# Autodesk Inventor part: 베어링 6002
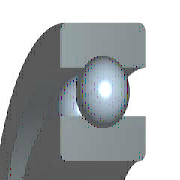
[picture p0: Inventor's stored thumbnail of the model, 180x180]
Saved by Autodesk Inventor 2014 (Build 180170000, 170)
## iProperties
IsCustomPart: 0
Created: 2012-02
Part Number: 베어링 6002
Material: 강철, 연강
Description: 깊은 그루브 볼 베어링
Document SubType Name: Modeling
Standard: KS B 2023
Designer: mduedu
Standards Organization: KS
Language: ko-KR
Size Designation: 6002 - 15 x 32 x 9
Categories: <MemberInstance><Categories><Category DisplayName="샤프트 부품" InternalName="7f7aeb1f-a693-4053-b835-cee3144e0d98" Mnemonic="SHFT"><Category DisplayName="베어링" Inter
Density: 7.86 g/cm^3
Mass: 29.8124 g
Surface Area: 39.9079 cm^2
Volume: 3.79293 cm^3
Appearance: 노란색
Author: mduedu
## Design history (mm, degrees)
sketch "스케치" dims "d0" = 4.42 (= -0.26 x WD + 0.26 x BD)
  geometry: L1 (2.29, 11.75)-(6.71, 11.75); L2 (4.5, 11.75)-(4.5, 9.54); L3 (4.5, 11.75)-(4.5, 13.96); L4 (2.858, 10.271)-(0, 10.271); L5 (0, 7.5)-(9, 7.5); L6 (2.858, 13.229)-(0, 13.229); L7 (0, 16)-(9, 16); L8 (9, 7.5)-(9, 10.271); L9 (6.142, 10.271)-(9, 10.271); L10 (6.142, 13.229)-(9, 13.229); L11 (9, 16)-(9, 13.229); L12 (-1.4, 0)-(8.4, 0) reference; L13 (0, -0.3)-(0, 5.3) reference
  constraints: 22 end point, 4 point on line, 2 collinear, 2 perpendicular, 2 symmetric about line, 1 midpoint, 1 parallel, 14 other
  dimensions: "d9" = 15 diameter of L5 L12 (= WD); "d11" = 32 diameter of L7 L12 (= BD); "d12" = 9 distance between parallel lines of L8 L13 (= KB); "d13" = 20.542 diameter of L9 L12 (= 0.326 x BD + 0.674 x WD)
revolve "본체" stored, may be unused: angle "d6" = 90 deg
revolve "볼" stored, may be unused: angle "d7" = 90 deg
pattern_circular "IDS_ARRAYBALL[SIMPL:T]" dims angle "d3" = 360 deg
body "Solid1"
fillet "모깎기1" dims "d1" = 0.3 (= KRS)
other parameters: "WD" = 15 [user parameter; used in 5 equation terms], "BD" = 32 [user parameter; used in 5 equation terms], "KB" = 9 [user parameter; used in 1 equation term], "KRS" = 0.3 [user parameter; used in 1 equation term], "d4" = 0, "d5" = 0, "d8" = 0, "d14" = 0, "d15" = 0, "BBA" = 0 [user parameter], "BC0" = 2850000 [user parameter], "BC" = 5590000 [user parameter], "BR" = 16 (= 0.5 x BD) [user parameter], "WR" = 7.5 (= 0.5 x WD) [user parameter]
